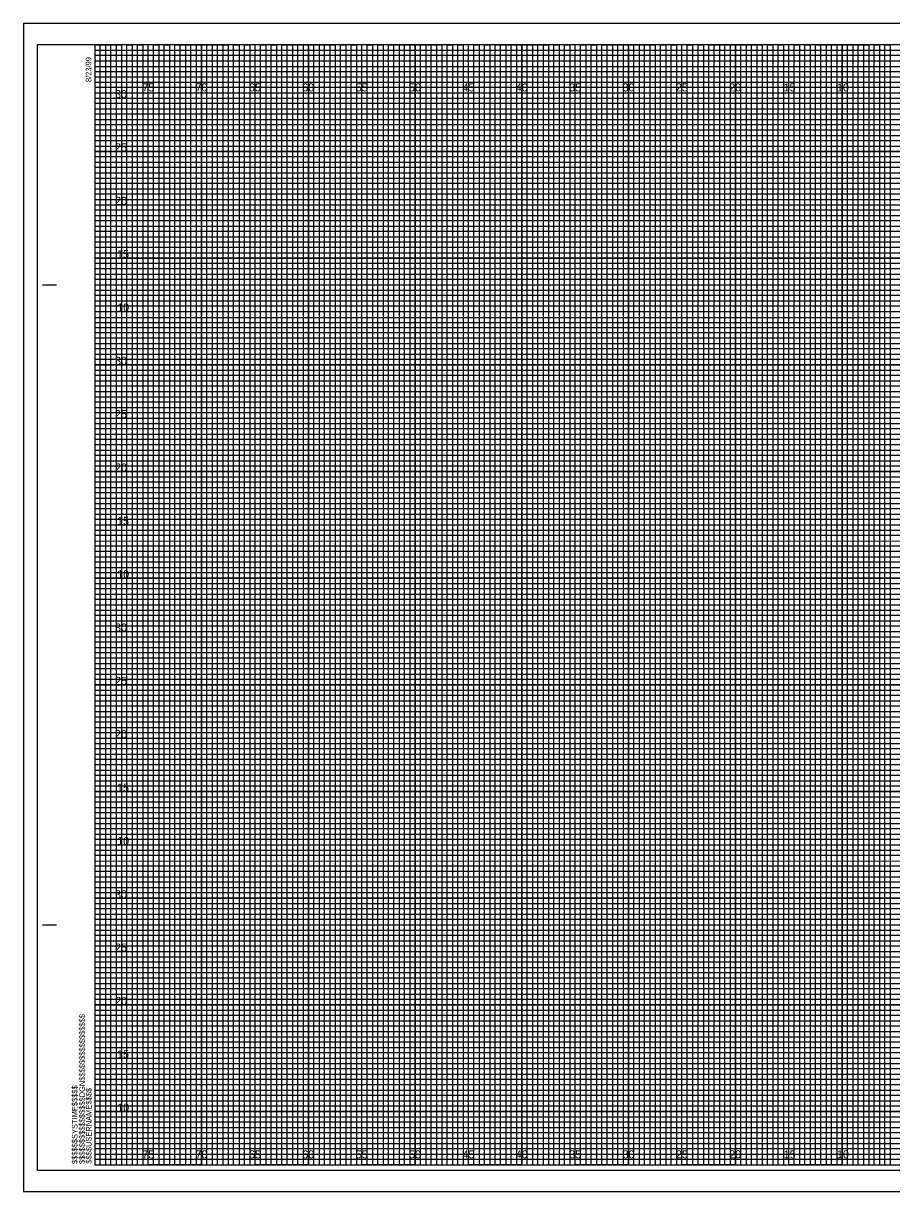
# Model space of a CAD drawing. Extents: x -7 to 162, y 107 to 217.
# Drawn here: x -6.7 to 74.6, y 107.5 to 217 of the extents above; entities that cross this region are included whole.
import ezdxf

# ---------------------------------------------------------------- set-up
doc = ezdxf.new("R2010")
doc.units = 0
for name, color, linetype in [('Exist Cross Section Cell', 7, 'Continuous'), ('Exist XS Center Line Elevation Label', 7, 'Continuous'), ('Exist XS Ground Line', 7, 'Continuous'), ('Prop CMT Pvmt Course 2', 7, 'Continuous'), ('Prop CMT Pvmt Course 3', 7, 'Continuous'), ('Prop CMT Pvmt Surface', 7, 'Continuous'), ('Prop CMT Pvmt Surface Shoulder', 7, 'Continuous'), ('Prop CMT Shld Paved Course 1', 7, 'Continuous'), ('Prop CMT Shld Paved Course 2', 7, 'Continuous'), ('Prop CMT Subgrade Earthwork', 7, 'Continuous'), ('Scratch_Level_0', 7, 'Continuous')]:
    doc.layers.add(name, color=color, linetype=linetype)

msp = doc.modelspace()

# ---------------------------------------------------------------- linework, layer by layer
at = {"layer": 'Exist XS Center Line Elevation Label'}
for points in [[(0, 215), (2.5, 215), (2.5, 110), (7.5, 110), (7.5, 215), (12.5, 215), (12.5, 110), (17.5, 110), (17.5, 215), (22.5, 215), (22.5, 110), (27.5, 110), (27.5, 215), (32.5, 215), (32.5, 110), (37.5, 110), (37.5, 215), (42.5, 215), (42.5, 110), (47.5, 110), (47.5, 215), (52.5, 215), (52.5, 110), (57.5, 110), (57.5, 215), (62.5, 215), (62.5, 110), (67.5, 110), (67.5, 215), (72.5, 215), (72.5, 110), (77.5, 110)], [(0, 212.5), (137.5, 212.5)], [(0, 202.5), (160, 202.5), (160, 207.5), (0, 207.5)], [(0, 192.5), (160, 192.5), (160, 197.5), (0, 197.5)], [(0, 182.5), (160, 182.5), (160, 187.5), (0, 187.5)], [(0, 172.5), (160, 172.5), (160, 177.5), (0, 177.5)], [(0, 162.5), (160, 162.5), (160, 167.5), (0, 167.5)], [(0, 152.5), (160, 152.5), (160, 157.5), (0, 157.5)], [(0, 142.5), (160, 142.5), (160, 147.5), (0, 147.5)], [(0, 132.5), (160, 132.5), (160, 137.5), (0, 137.5)], [(0, 122.5), (160, 122.5), (160, 127.5), (0, 127.5)], [(0, 112.5), (160, 112.5), (160, 117.5), (0, 117.5)]]:
    msp.add_lwpolyline(points, dxfattribs=at)
at = {"layer": 'Exist XS Ground Line'}
for p, q in [((5, 215), (0, 215)), ((5, 110), (5, 215)), ((15, 215), (10, 215)), ((10, 215), (10, 110)), ((15, 110), (15, 215)), ((25, 215), (20, 215)), ((20, 215), (20, 110)), ((25, 110), (25, 215)), ((35, 215), (30, 215)), ((30, 215), (30, 110)), ((35, 110), (35, 215)), ((45, 215), (40, 215)), ((40, 215), (40, 110)), ((45, 110), (45, 215)), ((55, 215), (50, 215)), ((50, 215), (50, 110)), ((55, 110), (55, 215)), ((65, 215), (60, 215)), ((60, 215), (60, 110)), ((65, 110), (65, 215)), ((75, 215), (70, 215)), ((70, 215), (70, 110)), ((10, 110), (5, 110)), ((20, 110), (15, 110)), ((30, 110), (25, 110)), ((40, 110), (35, 110)), ((50, 110), (45, 110)), ((60, 110), (55, 110)), ((70, 110), (65, 110))]:
    msp.add_line(p, q, dxfattribs=at)
for points in [[(0, 210), (160, 210), (160, 205), (0, 205)], [(0, 200), (160, 200), (160, 195), (0, 195)], [(0, 190), (160, 190), (160, 185), (0, 185)], [(0, 180), (160, 180), (160, 175), (0, 175)], [(0, 170), (160, 170), (160, 165), (0, 165)], [(0, 160), (160, 160), (160, 155), (0, 155)], [(0, 150), (160, 150), (160, 145), (0, 145)], [(0, 140), (160, 140), (160, 135), (0, 135)], [(0, 130), (160, 130), (160, 125), (0, 125)], [(0, 120), (160, 120), (160, 115), (0, 115)]]:
    msp.add_lwpolyline(points, dxfattribs=at)
at = {"layer": 'Prop CMT Pvmt Course 2'}
msp.add_lwpolyline([(-6.7, 107.5), (161.65, 107.5), (161.65, 217), (-6.7, 217)], close=True, dxfattribs=at)
at = {"layer": 'Prop CMT Pvmt Course 3'}
msp.add_lwpolyline([(-5.4, 109.5), (161.2, 109.5), (161.2, 215), (-5.4, 215)], close=True, dxfattribs=at)
at = {"layer": 'Prop CMT Pvmt Surface'}
for p, q in [((161.65, 217), (-6.7, 217)), ((-6.7, 217), (-6.7, 107.5)), ((-6.7, 107.5), (161.65, 107.5))]:
    msp.add_line(p, q, dxfattribs=at)
at = {"layer": 'Prop CMT Shld Paved Course 1'}
for p, q in [((-4.9, 192.5), (-3.65, 192.5)), ((-4.85, 192.5), (-3.6, 192.5)), ((-4.9, 132.5), (-3.65, 132.5)), ((-4.85, 132.5), (-3.6, 132.5)), ((0, 110), (0, 110)), ((0, 110), (0, 110)), ((0, 110), (0, 110)), ((0, 110), (0, 110)), ((0, 110), (0, 110)), ((0, 110), (0, 110)), ((0, 110), (0, 110))]:
    msp.add_line(p, q, dxfattribs=at)
msp.add_lwpolyline([(160, 215), (0, 215), (0, 110), (160, 110)], close=True, dxfattribs=at)
at = {"layer": 'Prop CMT Shld Paved Course 2'}
for points in [[(0, 110), (0.5, 110), (0.5, 215), (1, 215), (1, 110)], [(1, 110), (1.5, 110), (1.5, 215), (2, 215), (2, 110)], [(2.5, 110), (3, 110), (3, 215), (3.5, 215), (3.5, 110)], [(3.5, 110), (4, 110), (4, 215), (4.5, 215), (4.5, 110)], [(5, 110), (5.5, 110), (5.5, 215), (6, 215), (6, 110)], [(6, 110), (6.5, 110), (6.5, 215), (7, 215), (7, 110)], [(7.5, 110), (8, 110), (8, 215), (8.5, 215), (8.5, 110)], [(8.5, 110), (9, 110), (9, 215), (9.5, 215), (9.5, 110)], [(10, 110), (10.5, 110), (10.5, 215), (11, 215), (11, 110)], [(11, 110), (11.5, 110), (11.5, 215), (12, 215), (12, 110)], [(12.5, 110), (13, 110), (13, 215), (13.5, 215), (13.5, 110)], [(13.5, 110), (14, 110), (14, 215), (14.5, 215), (14.5, 110)], [(15, 110), (15.5, 110), (15.5, 215), (16, 215), (16, 110)], [(16, 110), (16.5, 110), (16.5, 215), (17, 215), (17, 110)], [(17.5, 110), (18, 110), (18, 215), (18.5, 215), (18.5, 110)], [(18.5, 110), (19, 110), (19, 215), (19.5, 215), (19.5, 110)], [(20, 110), (20.5, 110), (20.5, 215), (21, 215), (21, 110)], [(21, 110), (21.5, 110), (21.5, 215), (22, 215), (22, 110)], [(22.5, 110), (23, 110), (23, 215), (23.5, 215), (23.5, 110)], [(23.5, 110), (24, 110), (24, 215), (24.5, 215), (24.5, 110)], [(25, 110), (25.5, 110), (25.5, 215), (26, 215), (26, 110)], [(26, 110), (26.5, 110), (26.5, 215), (27, 215), (27, 110)], [(27.5, 110), (28, 110), (28, 215), (28.5, 215), (28.5, 110)], [(28.5, 110), (29, 110), (29, 215), (29.5, 215), (29.5, 110)], [(30, 110), (30.5, 110), (30.5, 215), (31, 215), (31, 110)], [(31, 110), (31.5, 110), (31.5, 215), (32, 215), (32, 110)], [(32.5, 110), (33, 110), (33, 215), (33.5, 215), (33.5, 110)], [(33.5, 110), (34, 110), (34, 215), (34.5, 215), (34.5, 110)], [(35, 110), (35.5, 110), (35.5, 215), (36, 215), (36, 110)], [(36, 110), (36.5, 110), (36.5, 215), (37, 215), (37, 110)], [(37.5, 110), (38, 110), (38, 215), (38.5, 215), (38.5, 110)], [(38.5, 110), (39, 110), (39, 215), (39.5, 215), (39.5, 110)], [(40, 110), (40.5, 110), (40.5, 215), (41, 215), (41, 110)], [(41, 110), (41.5, 110), (41.5, 215), (42, 215), (42, 110)], [(42.5, 110), (43, 110), (43, 215), (43.5, 215), (43.5, 110)], [(43.5, 110), (44, 110), (44, 215), (44.5, 215), (44.5, 110)], [(45, 110), (45.5, 110), (45.5, 215), (46, 215), (46, 110)], [(46, 110), (46.5, 110), (46.5, 215), (47, 215), (47, 110)], [(47.5, 110), (48, 110), (48, 215), (48.5, 215), (48.5, 110)], [(48.5, 110), (49, 110), (49, 215), (49.5, 215), (49.5, 110)], [(50, 110), (50.5, 110), (50.5, 215), (51, 215), (51, 110)], [(51, 110), (51.5, 110), (51.5, 215), (52, 215), (52, 110)], [(52.5, 110), (53, 110), (53, 215), (53.5, 215), (53.5, 110)], [(53.5, 110), (54, 110), (54, 215), (54.5, 215), (54.5, 110)], [(55, 110), (55.5, 110), (55.5, 215), (56, 215), (56, 110)], [(56, 110), (56.5, 110), (56.5, 215), (57, 215), (57, 110)], [(57.5, 110), (58, 110), (58, 215), (58.5, 215), (58.5, 110)], [(58.5, 110), (59, 110), (59, 215), (59.5, 215), (59.5, 110)], [(60, 110), (60.5, 110), (60.5, 215), (61, 215), (61, 110)], [(61, 110), (61.5, 110), (61.5, 215), (62, 215), (62, 110)], [(62.5, 110), (63, 110), (63, 215), (63.5, 215), (63.5, 110)], [(63.5, 110), (64, 110), (64, 215), (64.5, 215), (64.5, 110)], [(65, 110), (65.5, 110), (65.5, 215), (66, 215), (66, 110)], [(66, 110), (66.5, 110), (66.5, 215), (67, 215), (67, 110)], [(67.5, 110), (68, 110), (68, 215), (68.5, 215), (68.5, 110)], [(68.5, 110), (69, 110), (69, 215), (69.5, 215), (69.5, 110)], [(70, 110), (70.5, 110), (70.5, 215), (71, 215), (71, 110)], [(71, 110), (71.5, 110), (71.5, 215), (72, 215), (72, 110)], [(72.5, 110), (73, 110), (73, 215), (73.5, 215), (73.5, 110)], [(73.5, 110), (74, 110), (74, 215), (74.5, 215), (74.5, 110)]]:
    msp.add_lwpolyline(points, dxfattribs=at)
at = {"layer": 'Prop CMT Subgrade Earthwork'}
for p, q in [((5, 110), (5, 215)), ((10, 110), (10, 215)), ((15, 110), (15, 215)), ((20, 110), (20, 215)), ((25, 110), (25, 215)), ((30, 110), (30, 215)), ((35, 110), (35, 215)), ((40, 110), (40, 215)), ((45, 110), (45, 215)), ((50, 110), (50, 215)), ((55, 110), (55, 215)), ((60, 110), (60, 215)), ((65, 110), (65, 215)), ((70, 110), (70, 215)), ((0, 210), (160, 210)), ((0, 205), (160, 205)), ((0, 200), (160, 200)), ((0, 195), (160, 195)), ((0, 190), (160, 190)), ((0, 185), (160, 185)), ((0, 180), (160, 180)), ((0, 175), (160, 175)), ((0, 170), (160, 170)), ((0, 165), (160, 165)), ((0, 160), (160, 160)), ((0, 155), (160, 155)), ((0, 150), (160, 150)), ((0, 145), (160, 145)), ((0, 140), (160, 140)), ((0, 135), (160, 135)), ((0, 130), (160, 130)), ((0, 125), (160, 125)), ((0, 120), (160, 120)), ((0, 115), (160, 115))]:
    msp.add_line(p, q, dxfattribs=at)
at = {"layer": 'Scratch_Level_0'}
for p, q in [((0, 214.5), (130, 214.5)), ((130, 213.99), (0, 213.99)), ((0, 213.99), (0, 213.5)), ((0, 213.5), (130, 213.5)), ((130, 212.94), (0, 212.94)), ((0, 212.94), (0, 212)), ((0, 212), (160, 212))]:
    msp.add_line(p, q, dxfattribs=at)
for points in [[(0, 211.5), (135, 211.5), (160, 211.5), (160, 211), (0, 211)], [(0, 210.5), (160, 210.5), (160, 209.5), (0, 209.5)], [(0, 209), (160, 209), (160, 208.5), (0, 208.49)], [(0, 208), (160, 208), (160, 207), (0, 207)], [(0, 206.5), (160, 206.5), (160, 206), (0, 206)], [(0, 205.5), (160, 205.5), (160, 204.5), (0, 204.5)], [(0, 204), (160, 204), (160, 203.5), (0, 203.5)], [(0, 203), (160, 203), (160, 202), (0, 202)], [(0, 201.5), (160, 201.5), (160, 201), (0, 201)], [(0, 200.5), (160, 200.5), (160, 199.5), (0, 199.5)], [(0, 199), (160, 199), (160, 198.5), (0, 198.5)], [(0, 198), (160, 198), (160, 196.97), (160, 196.5), (160, 196), (0, 196)], [(0, 197), (160, 197), (160, 196.5), (0, 196.5)], [(0, 195.5), (160, 195.5), (160, 194.5), (0, 194.52)], [(0, 194.52), (160, 194.5), (160, 194), (0, 194)], [(0, 193.5), (160, 193.5), (160, 193), (0, 193)], [(0, 192), (160, 192), (160, 191.5), (0, 191.5)], [(0, 191), (160, 191), (160, 190.5), (0, 190.5)], [(-0.04, 189.44), (160, 189.44), (160, 188.94), (-0.04, 188.94)], [(0, 188.5), (160, 188.5), (160, 188), (0, 188)], [(0, 187), (160, 187), (160, 186.5), (0, 186.5)], [(0, 186), (160, 186), (160, 185.5), (0, 185.5)], [(0, 184.5), (160, 184.5), (160, 184), (0, 184)], [(0, 183.5), (160, 183.5), (160, 183), (0, 183)], [(0, 182), (160, 182), (160, 181.5), (0, 181.5)], [(0, 181), (160, 181), (160, 180.5), (0, 180.5)], [(0, 179.5), (160, 179.5), (160, 178.99), (0, 179)], [(0, 178.5), (160, 178.5), (160, 178), (0, 178)], [(0, 177), (160, 177), (160, 176.5), (0, 176.5)], [(0, 176), (160, 176), (160, 175.5), (0, 175.5)], [(0, 174.5), (160, 174.5), (160, 174), (0, 174)], [(0, 173.5), (160, 173.5), (160, 173), (0, 173)], [(0, 172), (160, 172), (160, 171.5), (0, 171.5)], [(0, 171), (160, 171), (160, 170.5), (0, 170.5)], [(0, 169.5), (160, 169.5), (160, 169), (0, 169)], [(0, 168.5), (160.03, 168.46), (160, 168), (0, 168)], [(0, 167), (160, 167), (160, 166.5), (0, 166.5)], [(0, 166), (160, 166), (160, 165.5), (0, 165.5)], [(0, 164.5), (160, 164.5), (160, 164), (0, 164)], [(0, 163.5), (160, 163.5), (160, 163), (0, 163)], [(0, 162), (160, 162), (160, 161.5), (0, 161.5)], [(0, 161), (160, 161), (160, 160.5), (0, 160.5)], [(0, 159.5), (160, 159.5), (160, 159), (0, 159)], [(0, 158.5), (160, 158.5), (160, 158), (0, 158)], [(0, 157), (160, 157), (160, 156.5), (0, 156.5)], [(0, 156), (160, 156), (160, 155.5), (0, 155.5)], [(0, 154.5), (160, 154.5), (160, 154), (0, 154)], [(0, 153.5), (160, 153.5), (160, 153), (0, 153)], [(0, 152), (160, 152), (160, 151.5), (0, 151.5)], [(0, 151), (160, 151), (160, 150.5), (0, 150.5)], [(0, 149.5), (160, 149.5), (160, 148.99), (0, 149)], [(0, 148.5), (160, 148.5), (160, 148), (0, 148)], [(0, 147), (160, 147), (160, 146.5), (0, 146.5)], [(0, 146), (160, 146), (160, 145.5), (0, 145.5)], [(0, 144.5), (160, 144.5), (160, 144), (0, 144)], [(0, 143.5), (160, 143.5), (160, 143), (0, 143)], [(0, 142), (160, 142), (160, 141.5), (0, 141.5)], [(0, 141), (160, 141), (160, 140.5), (0, 140.5)], [(0, 139.5), (160, 139.5), (160, 139), (0, 139)], [(0, 138.5), (160.03, 138.46), (160, 138), (0, 138)], [(0, 137), (160, 137), (160, 136.5), (0, 136.5)], [(0, 136), (160, 136), (160, 135.5), (0, 135.5)], [(0, 134.5), (160, 134.5), (160, 134), (0, 134)], [(0, 133.5), (160, 133.5), (160, 133), (0, 133)], [(0, 132), (160, 132), (160, 131.5), (0, 131.5)], [(0, 131), (160, 131), (160, 130.5), (0, 130.5)], [(0, 129.5), (160, 129.5), (160, 129), (0, 129)], [(0, 128.5), (160, 128.5), (160, 128), (0, 128)], [(0, 127), (160, 127), (160, 126.5), (0, 126.5)], [(0, 126), (160, 126), (160, 125.5), (0, 125.5)], [(0, 124.5), (160, 124.5), (160, 124), (0, 124)], [(0, 123.5), (160, 123.5), (160, 123), (0, 123)], [(0, 122), (160, 122), (160, 121.5), (0, 121.5)], [(0, 121), (160, 121), (160, 120.5), (0, 120.5)], [(0, 119.5), (160, 119.5), (160, 119), (0, 119)], [(0, 118.5), (160, 118.5), (160, 118), (0, 118)], [(0, 117), (160, 117), (160, 116.5), (0, 116.5)], [(0, 116), (160, 116), (160, 115.5), (0, 115.5)], [(0, 114.5), (160, 114.5), (160, 114), (0, 114)], [(0, 113.5), (160, 113.5), (160, 113), (0, 113)], [(0, 112), (160, 112), (160, 111.5), (0, 111.5)], [(0, 111), (160, 111), (160, 110.5), (0, 110.5)]]:
    msp.add_lwpolyline(points, dxfattribs=at)

# ---------------------------------------------------------------- texts
at = {"layer": 'Exist Cross Section Cell'}
for s, p in [('75', (4.44, 210.62)), ('70', (9.43, 210.62)), ('65', (14.44, 210.62)), ('60', (19.43, 210.62)), ('55', (24.44, 210.62)), ('50', (29.43, 210.62)), ('45', (34.44, 210.62)), ('40', (39.43, 210.62)), ('35', (44.44, 210.62)), ('30', (49.43, 210.62)), ('25', (54.44, 210.62)), ('20', (59.43, 210.62)), ('15', (64.53, 210.62)), ('10', (69.52, 210.62)), ('75', (4.44, 110.62)), ('70', (9.43, 110.62)), ('65', (14.44, 110.62)), ('60', (19.43, 110.62)), ('55', (24.44, 110.62)), ('50', (29.43, 110.62)), ('45', (34.44, 110.62)), ('40', (39.43, 110.62)), ('35', (44.44, 110.62)), ('30', (49.43, 110.62)), ('25', (54.44, 110.62)), ('20', (59.43, 110.62)), ('15', (64.53, 110.62)), ('10', (69.52, 110.62))]:
    msp.add_text(s, height=0.75, dxfattribs=at).set_placement(p)
at = {"layer": 'Prop CMT Pvmt Surface Shoulder'}
for s, p in [('30', (1.89, 210)), ('25', (1.89, 205)), ('20', (1.9, 200)), ('15', (2.08, 195)), ('10', (2.09, 190)), ('30', (1.89, 185)), ('25', (1.89, 180)), ('20', (1.9, 175)), ('15', (2.08, 170)), ('10', (2.09, 165)), ('30', (1.89, 160)), ('25', (1.89, 155)), ('20', (1.9, 150)), ('15', (2.08, 145)), ('10', (2.09, 140)), ('30', (1.89, 135)), ('25', (1.89, 130)), ('20', (1.9, 125)), ('15', (2.08, 120)), ('10', (2.09, 115))]:
    msp.add_text(s, height=0.75, dxfattribs=at).set_placement(p)
at = {"layer": 'Prop CMT Shld Paved Course 1'}
for s, p in [('8/23/99', (-0.33, 211.5)), ('$$$$$$$$$$$$$$$$DGN$$$$$$$$$$$$$$$$', (-0.94, 110.09)), ('$$$$$$SYSTIME$$$$$', (-1.63, 110.09)), ('$$$$USERNAME$$$$', (-0.31, 110.12))]:
    msp.add_text(s, height=0.525, rotation=90, dxfattribs=at).set_placement(p)

doc.saveas('drawing.dxf')
